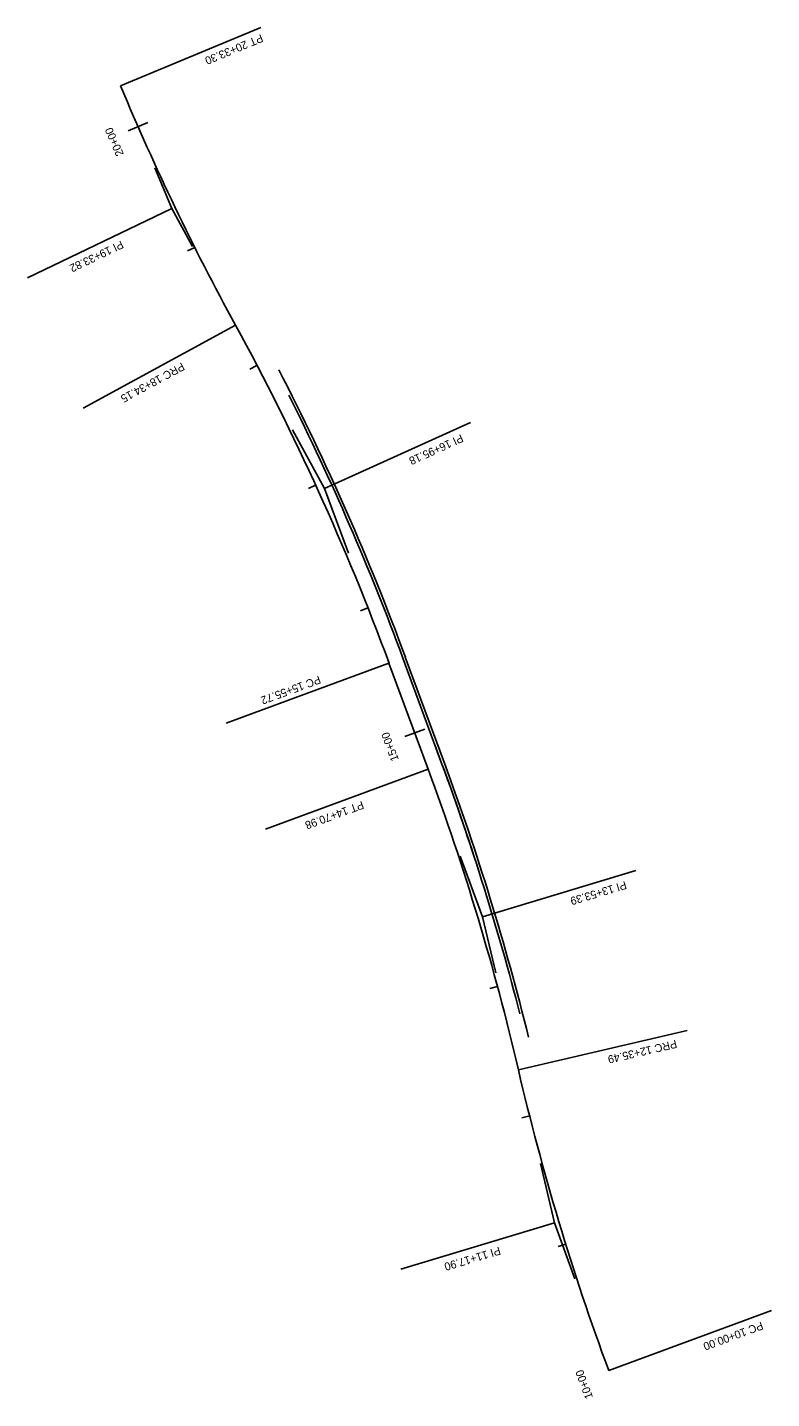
# Model space of a CAD drawing. Extents: x 955367 to 987800, y 1869413 to 1923417.
# Drawn here: x 987242 to 987800, y 1869413 to 1870441 of the extents above; entities that cross this region are included whole.
import ezdxf

# ---------------------------------------------------------------- set-up
doc = ezdxf.new("R2010")
doc.units = 0
for name, color, linetype in [('R_Horz Alg', 7, 'Continuous'), ('R_Horz Alg Annot', 7, 'Continuous'), ('R_Proposed Road', 7, 'Continuous')]:
    doc.layers.add(name, color=color, linetype=linetype)

msp = doc.modelspace()

# ---------------------------------------------------------------- linework, layer by layer
at = {"layer": 'R_Horz Alg'}
for p, q in [((987552.6, 1869889), (987523.2, 1869968.4)), ((987542.3, 1869885.1), (987512.9, 1869964.6)), ((987552.6, 1869889), (987547.3, 1869903.3)), ((987552.6, 1869889), (987547.3, 1869903.3))]:
    msp.add_line(p, q, dxfattribs=at)
for centre, radius, start, end in [((989074.6, 1871132.4), 1909.9, 202.6329, 208.6071), ((985721.2, 1869303.5), 1909.9, 20.254, 28.6071), ((985721.2, 1869303.5), 1920.9, 20.254, 26.6619), ((985750.5, 1869224), 1909.9, 13.1893, 20.254), ((985750.5, 1869224), 1920.9, 17.7717, 20.254), ((985750.5, 1869224), 1920.9, 14.4051, 20.254), ((985750.5, 1869224), 1920.9, 14.4051, 20.254), ((989469.4, 1870095.5), 1909.9, 193.1893, 200.254)]:
    msp.add_arc(centre, radius, start, end, dxfattribs=at)
at = {"layer": 'R_Horz Alg Annot'}
for p, q in [((987350.1, 1870305.4), (987337.4, 1870335.9)), ((987365.7, 1870277), (987350.1, 1870305.4)), ((987464.6, 1870095.5), (987440.7, 1870139.5)), ((987482.5, 1870047.1), (987464.6, 1870095.5)), ((987583.1, 1869774.5), (987566.3, 1869819.9)), ((987593, 1869732.4), (987583.1, 1869774.5)), ((987636.9, 1869545), (987626.4, 1869589.5)), ((987652.3, 1869503.1), (987636.9, 1869545))]:
    msp.add_line(p, q, dxfattribs=at)
for points in [[(987311.8, 1870397.4), (987416.8, 1870441.2)], [(987317.5, 1870363.6), (987332.2, 1870370)], [(987350.1, 1870305.4), (987241.9, 1870253.5)], [(987362, 1870273.6), (987367.3, 1870276.3)], [(987397.9, 1870217.9), (987283.7, 1870155.7)], [(987408.6, 1870185), (987413.9, 1870187.8)], [(987464.6, 1870095.5), (987573.9, 1870145.1)], [(987464.6, 1870095.5), (987573.9, 1870145.1)], [(987452.5, 1870095.5), (987457.9, 1870098)], [(987491.5, 1870003.8), (987497.1, 1870006)], [(987512.9, 1869964.6), (987391, 1869919.6)], [(987524.7, 1869909.6), (987539.7, 1869915.1)], [(987542.3, 1869885.1), (987420.3, 1869840.1)], [(987583.1, 1869774.5), (987698, 1869809.1)], [(987583.1, 1869774.5), (987698, 1869809.1)], [(987583.1, 1869774.5), (987698, 1869809.1)], [(987588.4, 1869720.7), (987594.2, 1869722.3)], [(987610, 1869659.8), (987736.5, 1869689.4)], [(987612.6, 1869623.8), (987618.4, 1869625.3)], [(987636.9, 1869545), (987521.9, 1869510.4)], [(987639.8, 1869527.3), (987645.5, 1869529)], [(987677.7, 1869434.4), (987799.6, 1869479.4)]]:
    msp.add_lwpolyline(points, dxfattribs=at)
at = {"layer": 'R_Proposed Road'}
for q in [(987525.1, 1869969.1), (987549.2, 1869904), (987549.2, 1869904)]:
    msp.add_line((987554.5, 1869889.6), q, dxfattribs=at)
for centre, start, end in [((985721.2, 1869303.5), 20.254, 27.2709), ((985750.5, 1869224), 13.8496, 20.254)]:
    msp.add_arc(centre, 1922.9, start, end, dxfattribs=at)

# ---------------------------------------------------------------- texts
at = {"layer": 'R_Horz Alg'}
for rotation, p in [(112.6329, (987312.4, 1870397.2)), (118.6071, (987398.5, 1870217.8)), (110.254, (987513.5, 1869964.4)), (110.254, (987542.9, 1869884.9)), (103.1893, (987610.6, 1869659.5)), (110.254, (987678.3, 1869434.1))]:
    msp.add_text('+', height=1, rotation=rotation, dxfattribs=at).set_placement(p)
at = {"layer": 'R_Horz Alg Annot'}
for s, rotation, p in [('PT 20+33.30', 202.6329, (987417, 1870436.3)), ('20+00', 113.6317, (987314.3, 1870346.2)), ('PI 19+33.82', 205.62, (987312.1, 1870281.6)), ('PRC 18+34.15', 208.6071, (987357.6, 1870190.2)), ('PI 16+95.18', 204.4306, (987566.9, 1870136.4)), ('PI 16+95.18', 204.4306, (987566.9, 1870136.4)), ('PC 15+55.72', 200.254, (987460.4, 1869955.4)), ('15+00', 110.254, (987520.4, 1869892.4)), ('PT 14+70.98', 200.254, (987492.7, 1869861.5)), ('PI 13+53.39', 196.7217, (987689.9, 1869801.4)), ('PI 13+53.39', 196.7217, (987689.9, 1869801.4)), ('PI 13+53.39', 196.7217, (987689.9, 1869801.4)), ('PRC 12+35.49', 193.1893, (987727.9, 1869682.3)), ('PI 11+17.90', 196.7217, (987595.5, 1869527.3)), ('PC 10+00.00', 200.254, (987792, 1869471.2)), ('10+00', 110.254, (987665.9, 1869414.4))]:
    msp.add_text(s, height=6, rotation=rotation, dxfattribs=at).set_placement(p)

doc.saveas('drawing.dxf')
